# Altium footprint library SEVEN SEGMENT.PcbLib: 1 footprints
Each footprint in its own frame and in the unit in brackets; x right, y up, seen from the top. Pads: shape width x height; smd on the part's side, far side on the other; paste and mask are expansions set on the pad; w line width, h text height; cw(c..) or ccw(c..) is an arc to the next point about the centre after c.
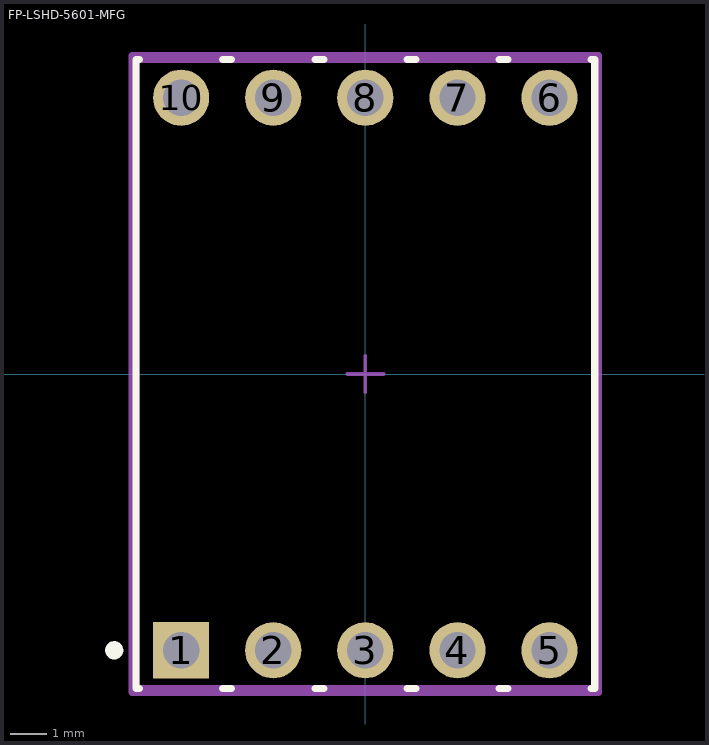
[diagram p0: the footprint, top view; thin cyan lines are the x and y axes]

## FP-LSHD-5601-MFG [mm]
pads (10):
  rect 1.55x1.55 hole 1 paste-1000 mask+0: 1(-5.08,-7.62)
  round 1.55 hole 1 paste-1000 mask+0: 2(-2.54,-7.62) 3(0,-7.62) 4(2.54,-7.62) 5(5.08,-7.62) 6(5.08,7.62) 7(2.54,7.62) 8(0,7.62) 9(-2.54,7.62) 10(-5.08,7.62)
Top Overlay:
  circle w0.25: c-6.925,-7.62 r0.125
  lines w0.2: -6.23,-8.675 -6.325,-8.675 -6.325,8.675 -6.23,8.675 ; -3.93,-8.675 -3.69,-8.675 ; -3.93,8.675 -3.69,8.675 ; -1.39,-8.675 -1.15,-8.675 ; -1.39,8.675 -1.15,8.675 ; 1.15,-8.675 1.39,-8.675 ; 1.15,8.675 1.39,8.675 ; 3.69,-8.675 3.93,-8.675 ; 3.69,8.675 3.93,8.675 ; 6.23,-8.675 6.325,-8.675 6.325,8.675 6.23,8.675
Top Assembly:
  lines w0.2: -6.425,-8.775 -6.425,8.775 6.425,8.775 6.425,-8.775 -6.425,-8.775
  text ".Designator" at 0,-0.001 h1
Top 3D Body:
  lines w0.2: -6.325,-8.675 -6.325,8.675 6.325,8.675 6.325,-8.675 -6.325,-8.675
Top Courtyard:
  lines w0.2: -6.425,-8.775 -6.425,8.775 6.425,8.775 6.425,-8.775 -6.425,-8.775
Top Component Center:
  lines w0.1: -0.5,0 0.5,0 ; 0,-0.5 0,0.5
3D body "Disp_Lite-On_LSHD-5601_eec.STEP": height 0.25, standoff 0, extent -6.425,-8.775 6.425,8.775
